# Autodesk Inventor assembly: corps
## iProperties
Shininess: 64.0
Length Units: 11269
Angle Units: 11279
Time Units: 11290
Mass Units: 11283
Length Display Precision: 3
Angle Display Precision: 2
Compacted: True
Created: 2005-01
Part Number: corps
Document SubType Name: Assembly
Designer: David
Manufacturer: Standard
Standards Organization: Custom
Density: 0.0
Volumn: 0.0
Area: 0.0
PropertySet Name: Model Information
Control State: 0
Master: False
Checked Out: False
Author: David
